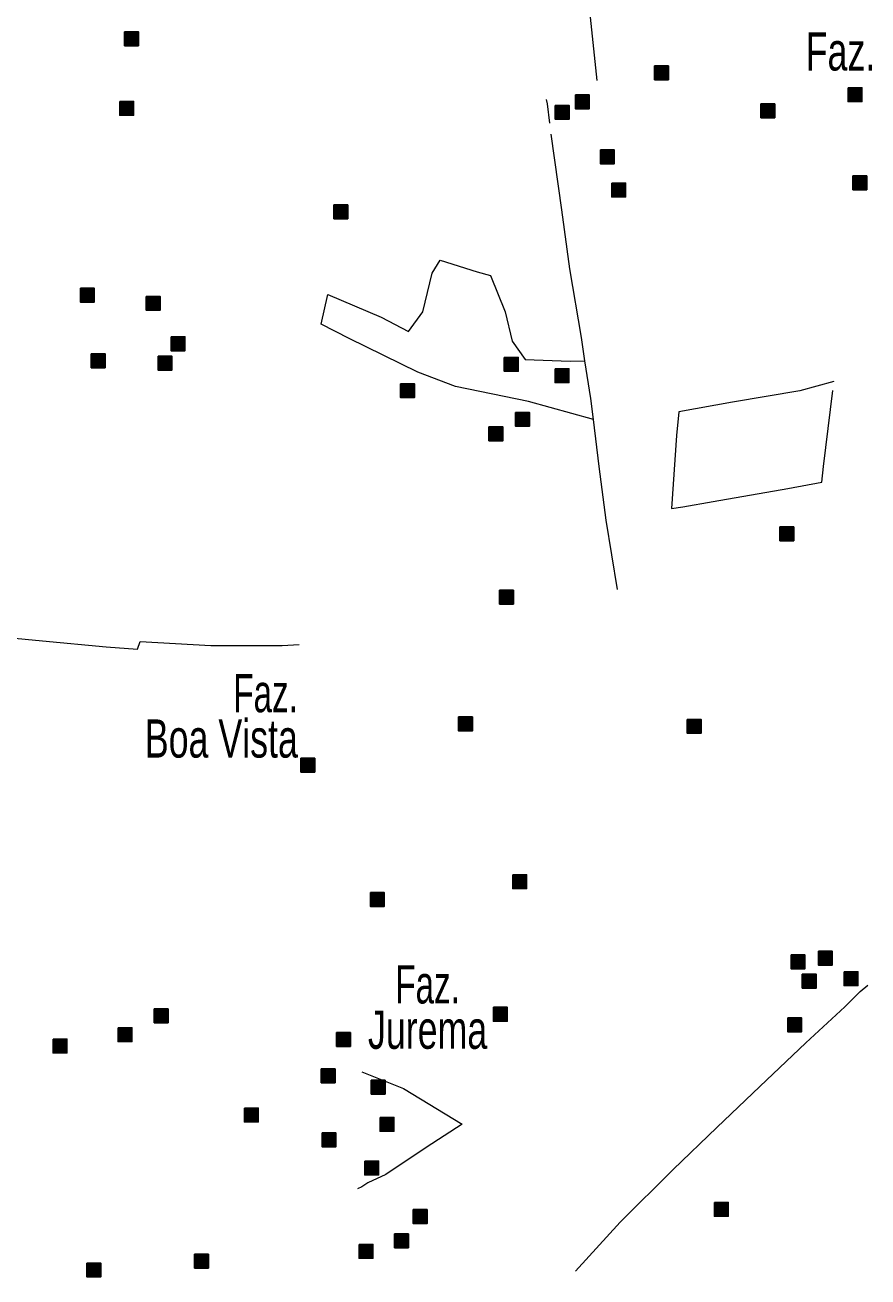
# Model space of a CAD drawing. Extents: x 445.6 to 500, y 8618.1 to 8673.4.
# Drawn here: x 484.01 to 487.54, y 8650.16 to 8655.41 of the extents above; entities that cross this region are included whole.
import ezdxf
from ezdxf.enums import TextEntityAlignment as Align

# ---------------------------------------------------------------- set-up
doc = ezdxf.new("R2010")
doc.units = 0
doc.header["$LTSCALE"] = 0.064
doc.linetypes.add('DOT_DASHED', pattern=[7.7, 5, -1.2, 0.3, -1.2])
doc.layers.add('2', color=7, linetype='Continuous', lineweight=25)
doc.layers.add('22', color=7, linetype='DOT_DASHED', lineweight=13)
doc.layers.add('61', color=7, linetype='Continuous')

msp = doc.modelspace()

# ---------------------------------------------------------------- hatches: boundary and pattern name
at = {"layer": '2'}
for points in [[(484.4289, 8655.3779), (484.4869, 8655.3779), (484.4869, 8655.3199), (484.4289, 8655.3199)], [(486.6489, 8655.2354), (486.7069, 8655.2354), (486.7069, 8655.1774), (486.6489, 8655.1774)], [(486.3178, 8655.1134), (486.3758, 8655.1134), (486.3758, 8655.0554), (486.3178, 8655.0554)], [(487.4595, 8655.1439), (487.5175, 8655.1439), (487.5175, 8655.0859), (487.4595, 8655.0859)], [(484.4087, 8655.0866), (484.4667, 8655.0866), (484.4667, 8655.0286), (484.4087, 8655.0286)], [(486.2334, 8655.0694), (486.2914, 8655.0694), (486.2914, 8655.0114), (486.2334, 8655.0114)], [(487.0947, 8655.0762), (487.1527, 8655.0762), (487.1527, 8655.0182), (487.0947, 8655.0182)], [(486.4225, 8654.883), (486.4805, 8654.883), (486.4805, 8654.825), (486.4225, 8654.825)], [(486.4698, 8654.7441), (486.5278, 8654.7441), (486.5278, 8654.6861), (486.4698, 8654.6861)], [(487.4798, 8654.7746), (487.5378, 8654.7746), (487.5378, 8654.7166), (487.4798, 8654.7166)], [(485.3061, 8654.6527), (485.3641, 8654.6527), (485.3641, 8654.5947), (485.3061, 8654.5947)], [(484.2441, 8654.3039), (484.3021, 8654.3039), (484.3021, 8654.2459), (484.2441, 8654.2459)], [(484.5201, 8654.27), (484.5781, 8654.27), (484.5781, 8654.212), (484.5201, 8654.212)], [(484.6238, 8654.1004), (484.6818, 8654.1004), (484.6818, 8654.0424), (484.6238, 8654.0424)], [(484.2894, 8654.0292), (484.3474, 8654.0292), (484.3474, 8653.9712), (484.2894, 8653.9712)], [(484.5698, 8654.0191), (484.6278, 8654.0191), (484.6278, 8653.9611), (484.5698, 8653.9611)], [(486.0198, 8654.0144), (486.0778, 8654.0144), (486.0778, 8653.9564), (486.0198, 8653.9564)], [(486.2326, 8653.967), (486.2906, 8653.967), (486.2906, 8653.909), (486.2326, 8653.909)], [(485.585, 8653.904), (485.643, 8653.904), (485.643, 8653.846), (485.585, 8653.846)], [(486.0671, 8653.7841), (486.1251, 8653.7841), (486.1251, 8653.7261), (486.0671, 8653.7261)], [(485.9556, 8653.7231), (486.0136, 8653.7231), (486.0136, 8653.6651), (485.9556, 8653.6651)], [(487.1743, 8653.3042), (487.2323, 8653.3042), (487.2323, 8653.2462), (487.1743, 8653.2462)], [(485.9996, 8653.0387), (486.0576, 8653.0387), (486.0576, 8652.9807), (485.9996, 8652.9807)], [(485.8281, 8652.508), (485.8861, 8652.508), (485.8861, 8652.45), (485.8281, 8652.45)], [(486.7859, 8652.4979), (486.8439, 8652.4979), (486.8439, 8652.4399), (486.7859, 8652.4399)], [(485.1676, 8652.3352), (485.2256, 8652.3352), (485.2256, 8652.2772), (485.1676, 8652.2772)], [(486.0553, 8651.847), (486.1133, 8651.847), (486.1133, 8651.789), (486.0553, 8651.789)], [(485.459, 8651.7725), (485.517, 8651.7725), (485.517, 8651.7145), (485.459, 8651.7145)], [(487.2207, 8651.5116), (487.2787, 8651.5116), (487.2787, 8651.4536), (487.2207, 8651.4536)], [(487.3352, 8651.5265), (487.3932, 8651.5265), (487.3932, 8651.4685), (487.3352, 8651.4685)], [(487.268, 8651.4303), (487.326, 8651.4303), (487.326, 8651.3723), (487.268, 8651.3723)], [(487.4432, 8651.441), (487.5012, 8651.441), (487.5012, 8651.383), (487.4432, 8651.383)], [(484.5537, 8651.2854), (484.6117, 8651.2854), (484.6117, 8651.2274), (484.5537, 8651.2274)], [(485.9738, 8651.2919), (486.0318, 8651.2919), (486.0318, 8651.2339), (485.9738, 8651.2339)], [(487.2072, 8651.2473), (487.2652, 8651.2473), (487.2652, 8651.1893), (487.2072, 8651.1893)], [(484.4017, 8651.2067), (484.4597, 8651.2067), (484.4597, 8651.1487), (484.4017, 8651.1487)], [(485.3171, 8651.1864), (485.3751, 8651.1864), (485.3751, 8651.1284), (485.3171, 8651.1284)], [(484.1295, 8651.1592), (484.1875, 8651.1592), (484.1875, 8651.1012), (484.1295, 8651.1012)], [(485.2529, 8651.0339), (485.3109, 8651.0339), (485.3109, 8650.9759), (485.2529, 8650.9759)], [(485.4623, 8650.9865), (485.5203, 8650.9865), (485.5203, 8650.9285), (485.4623, 8650.9285)], [(484.9308, 8650.8697), (484.9888, 8650.8697), (484.9888, 8650.8117), (484.9308, 8650.8117)], [(485.4995, 8650.8306), (485.5575, 8650.8306), (485.5575, 8650.7726), (485.4995, 8650.7726)], [(485.2563, 8650.7662), (485.3143, 8650.7662), (485.3143, 8650.7082), (485.2563, 8650.7082)], [(485.4353, 8650.6477), (485.4933, 8650.6477), (485.4933, 8650.5897), (485.4353, 8650.5897)], [(485.638, 8650.4444), (485.696, 8650.4444), (485.696, 8650.3864), (485.638, 8650.3864)], [(486.8998, 8650.4749), (486.9578, 8650.4749), (486.9578, 8650.4169), (486.8998, 8650.4169)], [(485.5603, 8650.3427), (485.6183, 8650.3427), (485.6183, 8650.2847), (485.5603, 8650.2847)], [(485.4117, 8650.2987), (485.4697, 8650.2987), (485.4697, 8650.2407), (485.4117, 8650.2407)], [(484.2714, 8650.2205), (484.3294, 8650.2205), (484.3294, 8650.1625), (484.2714, 8650.1625)], [(484.7227, 8650.2574), (484.7807, 8650.2574), (484.7807, 8650.1994), (484.7227, 8650.1994)]]:
    msp.add_hatch(color=256, dxfattribs=at).paths.add_polyline_path(points)

# ---------------------------------------------------------------- linework, layer by layer
for points in [[(484.4289, 8655.3779), (484.4869, 8655.3779), (484.4869, 8655.3199), (484.4289, 8655.3199)], [(486.6489, 8655.2354), (486.7069, 8655.2354), (486.7069, 8655.1774), (486.6489, 8655.1774)], [(486.3178, 8655.1134), (486.3758, 8655.1134), (486.3758, 8655.0554), (486.3178, 8655.0554)], [(487.4595, 8655.1439), (487.5175, 8655.1439), (487.5175, 8655.0859), (487.4595, 8655.0859)], [(484.4087, 8655.0866), (484.4667, 8655.0866), (484.4667, 8655.0286), (484.4087, 8655.0286)], [(486.2334, 8655.0694), (486.2914, 8655.0694), (486.2914, 8655.0114), (486.2334, 8655.0114)], [(487.0947, 8655.0762), (487.1527, 8655.0762), (487.1527, 8655.0182), (487.0947, 8655.0182)], [(486.4225, 8654.883), (486.4805, 8654.883), (486.4805, 8654.825), (486.4225, 8654.825)], [(486.4698, 8654.7441), (486.5278, 8654.7441), (486.5278, 8654.6861), (486.4698, 8654.6861)], [(487.4798, 8654.7746), (487.5378, 8654.7746), (487.5378, 8654.7166), (487.4798, 8654.7166)], [(485.3061, 8654.6527), (485.3641, 8654.6527), (485.3641, 8654.5947), (485.3061, 8654.5947)], [(484.2441, 8654.3039), (484.3021, 8654.3039), (484.3021, 8654.2459), (484.2441, 8654.2459)], [(484.5201, 8654.27), (484.5781, 8654.27), (484.5781, 8654.212), (484.5201, 8654.212)], [(484.6238, 8654.1004), (484.6818, 8654.1004), (484.6818, 8654.0424), (484.6238, 8654.0424)], [(484.2894, 8654.0292), (484.3474, 8654.0292), (484.3474, 8653.9712), (484.2894, 8653.9712)], [(484.5698, 8654.0191), (484.6278, 8654.0191), (484.6278, 8653.9611), (484.5698, 8653.9611)], [(486.0198, 8654.0144), (486.0778, 8654.0144), (486.0778, 8653.9564), (486.0198, 8653.9564)], [(486.2326, 8653.967), (486.2906, 8653.967), (486.2906, 8653.909), (486.2326, 8653.909)], [(485.585, 8653.904), (485.643, 8653.904), (485.643, 8653.846), (485.585, 8653.846)], [(486.0671, 8653.7841), (486.1251, 8653.7841), (486.1251, 8653.7261), (486.0671, 8653.7261)], [(485.9556, 8653.7231), (486.0136, 8653.7231), (486.0136, 8653.6651), (485.9556, 8653.6651)], [(487.1743, 8653.3042), (487.2323, 8653.3042), (487.2323, 8653.2462), (487.1743, 8653.2462)], [(485.9996, 8653.0387), (486.0576, 8653.0387), (486.0576, 8652.9807), (485.9996, 8652.9807)], [(485.8281, 8652.508), (485.8861, 8652.508), (485.8861, 8652.45), (485.8281, 8652.45)], [(486.7859, 8652.4979), (486.8439, 8652.4979), (486.8439, 8652.4399), (486.7859, 8652.4399)], [(485.1676, 8652.3352), (485.2256, 8652.3352), (485.2256, 8652.2772), (485.1676, 8652.2772)], [(486.0553, 8651.847), (486.1133, 8651.847), (486.1133, 8651.789), (486.0553, 8651.789)], [(485.459, 8651.7725), (485.517, 8651.7725), (485.517, 8651.7145), (485.459, 8651.7145)], [(487.2207, 8651.5116), (487.2787, 8651.5116), (487.2787, 8651.4536), (487.2207, 8651.4536)], [(487.3352, 8651.5265), (487.3932, 8651.5265), (487.3932, 8651.4685), (487.3352, 8651.4685)], [(487.268, 8651.4303), (487.326, 8651.4303), (487.326, 8651.3723), (487.268, 8651.3723)], [(487.4432, 8651.441), (487.5012, 8651.441), (487.5012, 8651.383), (487.4432, 8651.383)], [(484.5537, 8651.2854), (484.6117, 8651.2854), (484.6117, 8651.2274), (484.5537, 8651.2274)], [(485.9738, 8651.2919), (486.0318, 8651.2919), (486.0318, 8651.2339), (485.9738, 8651.2339)], [(487.2072, 8651.2473), (487.2652, 8651.2473), (487.2652, 8651.1893), (487.2072, 8651.1893)], [(484.4017, 8651.2067), (484.4597, 8651.2067), (484.4597, 8651.1487), (484.4017, 8651.1487)], [(485.3171, 8651.1864), (485.3751, 8651.1864), (485.3751, 8651.1284), (485.3171, 8651.1284)], [(484.1295, 8651.1592), (484.1875, 8651.1592), (484.1875, 8651.1012), (484.1295, 8651.1012)], [(485.2529, 8651.0339), (485.3109, 8651.0339), (485.3109, 8650.9759), (485.2529, 8650.9759)], [(485.4623, 8650.9865), (485.5203, 8650.9865), (485.5203, 8650.9285), (485.4623, 8650.9285)], [(484.9308, 8650.8697), (484.9888, 8650.8697), (484.9888, 8650.8117), (484.9308, 8650.8117)], [(485.4995, 8650.8306), (485.5575, 8650.8306), (485.5575, 8650.7726), (485.4995, 8650.7726)], [(485.2563, 8650.7662), (485.3143, 8650.7662), (485.3143, 8650.7082), (485.2563, 8650.7082)], [(485.4353, 8650.6477), (485.4933, 8650.6477), (485.4933, 8650.5897), (485.4353, 8650.5897)], [(485.638, 8650.4444), (485.696, 8650.4444), (485.696, 8650.3864), (485.638, 8650.3864)], [(486.8998, 8650.4749), (486.9578, 8650.4749), (486.9578, 8650.4169), (486.8998, 8650.4169)], [(485.5603, 8650.3427), (485.6183, 8650.3427), (485.6183, 8650.2847), (485.5603, 8650.2847)], [(485.4117, 8650.2987), (485.4697, 8650.2987), (485.4697, 8650.2407), (485.4117, 8650.2407)], [(484.2714, 8650.2205), (484.3294, 8650.2205), (484.3294, 8650.1625), (484.2714, 8650.1625)], [(484.7227, 8650.2574), (484.7807, 8650.2574), (484.7807, 8650.1994), (484.7227, 8650.1994)]]:
    msp.add_lwpolyline(points, close=True, dxfattribs=at)
at = {"layer": '22'}
for points in [[(486.409, 8655.1735), (486.3622, 8655.6162), (486.2997, 8656.074), (486.2446, 8656.5548), (486.1931, 8656.9977), (486.1453, 8657.3867), (486.0864, 8657.822), (486.0643, 8657.9872), (486.0692, 8658.013)], [(486.3576, 8654.0005), (486.3424, 8654.0979), (486.2943, 8654.385), (486.2603, 8654.6328), (486.2101, 8654.9958), (486.2001, 8655.0766), (486.1966, 8655.0949)], [(486.3929, 8653.7538), (486.1212, 8653.829), (485.8151, 8653.8929), (485.6576, 8653.9522), (485.3698, 8654.0936), (485.2533, 8654.1529), (485.2807, 8654.2783), (485.5045, 8654.1825), (485.6187, 8654.1232), (485.6781, 8654.2053), (485.7169, 8654.3672), (485.7513, 8654.421), (485.9066, 8654.3731), (485.9614, 8654.3572), (486.0231, 8654.2044), (486.0529, 8654.0824), (486.1077, 8654.0049), (486.295, 8653.9981), (486.3576, 8654.0005)], [(486.3929, 8653.7538), (486.3824, 8653.8421), (486.3576, 8654.0005)], [(486.4938, 8653.0422), (486.4464, 8653.3331), (486.4164, 8653.5568), (486.3929, 8653.7538)], [(483.0014, 8652.9466), (483.2224, 8652.9201), (483.4934, 8652.89), (483.7974, 8652.8545), (484.0849, 8652.8271), (484.3522, 8652.8025), (484.4837, 8652.7916), (484.4946, 8652.8244), (484.7903, 8652.808), (485.0888, 8652.808), (485.1599, 8652.8117)], [(486.3178, 8650.1865), (486.5057, 8650.3918), (486.7271, 8650.6128), (486.9099, 8650.789), (487.0899, 8650.9604), (487.2824, 8651.1429), (487.446, 8651.2935), (487.5107, 8651.3586), (487.5428, 8651.3846)], [(485.4235, 8651.0219), (485.597, 8650.9515), (485.8437, 8650.8026), (485.6919, 8650.7052), (485.5238, 8650.5915), (485.4479, 8650.5563), (485.4235, 8650.54), (485.4048, 8650.5321)]]:
    msp.add_lwpolyline(points, dxfattribs=at)
msp.add_lwpolyline([(486.7677, 8653.3886), (486.8942, 8653.4101), (487.2069, 8653.4649), (487.3501, 8653.4911), (487.3573, 8653.5578), (487.4002, 8653.913), (487.257, 8653.8748), (486.9754, 8653.8272), (486.751, 8653.7866), (486.7415, 8653.6865), (486.72, 8653.3815)], close=True, dxfattribs=at)

# ---------------------------------------------------------------- texts
at = {"layer": '61', "width": 0.7}
msp.add_text('Faz. Roça Grande', height=0.16, dxfattribs=at).set_placement((487.2822, 8655.2159))
at = {"layer": '61'}
for s, width, p in [('Faz.', 0.65, (485.1551, 8652.5279)), ('Boa Vista', 0.7, (485.1551, 8652.3379))]:
    msp.add_text(s, height=0.16, dxfattribs=dict(at, width=width)).set_placement(p, align=Align.RIGHT)
for s, width, p in [('Faz.', 0.65, (485.6984, 8651.3082)), ('Jurema', 0.7, (485.6984, 8651.1182))]:
    msp.add_text(s, height=0.16, dxfattribs=dict(at, width=width)).set_placement(p, align=Align.CENTER)

doc.saveas('drawing.dxf')
